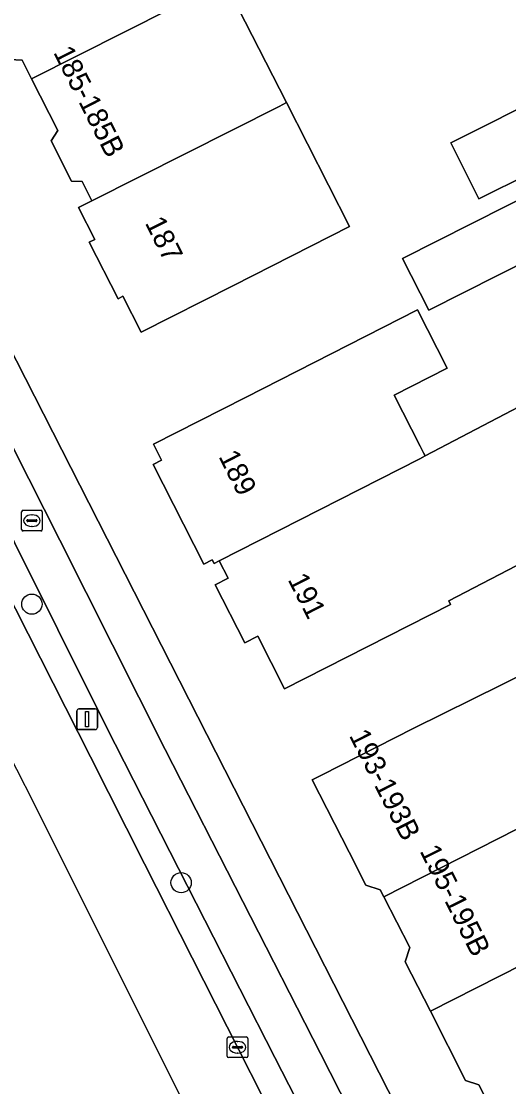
# Model space of a CAD drawing. Extents: x 162344 to 162869, y 381217 to 381818.
# Drawn here: x 162388.7 to 162412.2, y 381573.3 to 381624.8 of the extents above; entities that cross this region are included whole.
import ezdxf

# ---------------------------------------------------------------- set-up
doc = ezdxf.new("R2010")
doc.units = 0
for name, color, linetype in [('IMGEO_Berm_open', 7, 'Continuous'), ('IMGEO_Boom', 7, 'Continuous'), ('IMGEO_Brandkraan', 7, 'Continuous'), ('IMGEO_Erf', 7, 'Continuous'), ('IMGEO_Fietspad_open', 7, 'Continuous'), ('IMGEO_Kolk', 7, 'Continuous'), ('IMGEO_Lichtmast', 7, 'Continuous'), ('IMGEO_Pand', 7, 'Continuous'), ('IMGEO_Pand_nummerreeks', 7, 'Continuous'), ('IMGEO_Rijbaan_regionaal_gesloten', 7, 'Continuous'), ('IMGEO_Voetpad_open', 7, 'Continuous')]:
    doc.layers.add(name, color=color, linetype=linetype)

msp = doc.modelspace()

# ---------------------------------------------------------------- linework, layer by layer
at = {"layer": 'IMGEO_Berm_open'}
for points in [[(162358.654, 381655.431), (162360.733, 381651.139), (162362.48, 381647.434), (162367.291, 381637.935), (162369.471, 381633.629), (162370.915, 381630.775), (162376.144, 381620.551), (162378.309, 381616.304), (162381.2, 381610.636), (162383.842, 381605.454), (162387.066, 381599.034), (162387.783, 381597.606), (162391.996, 381589.28), (162394.619, 381584.098), (162396.915, 381579.56), (162402.557, 381568.4), (162406.049, 381561.587), (162408.71, 381556.396), (162409.049, 381555.709), (162410.306, 381556.355), (162407.33, 381562.188), (162400.899, 381574.731)], [(162400.899, 381574.731), (162395.837, 381584.693), (162393.201, 381589.881), (162392.517, 381591.227), (162388.339, 381599.637), (162387.808, 381600.705), (162382.464, 381611.316), (162380.864, 381614.494), (162379.579, 381616.989), (162374.942, 381625.996), (162370.754, 381634.243), (162367.724, 381640.204), (162364.002, 381647.524), (162361.111, 381653.216)]]:
    msp.add_lwpolyline(points, dxfattribs=at)
at = {"layer": 'IMGEO_Boom'}
for centre in [(162389.173, 381596.654), (162396.379, 381583.19)]:
    msp.add_circle(centre, 0.489, dxfattribs=at)
at = {"layer": 'IMGEO_Brandkraan'}
for p, q in [((162388.675, 381600.263), (162388.675, 381601.115)), ((162388.75, 381601.189), (162389.602, 381601.189)), ((162389.676, 381601.115), (162389.676, 381600.263)), ((162388.934, 381600.683), (162388.934, 381600.695)), ((162389.372, 381600.646), (162388.974, 381600.646)), ((162388.977, 381600.732), (162389.375, 381600.732)), ((162389.163, 381600.969), (162389.188, 381600.969)), ((162389.418, 381600.695), (162389.418, 381600.683)), ((162389.602, 381600.189), (162388.75, 381600.189)), ((162389.186, 381600.409), (162389.161, 381600.409))]:
    msp.add_line(p, q, dxfattribs=at)
for points in [[(162388.675, 381600.263), (162388.675, 381601.115)], [(162388.75, 381601.189), (162389.602, 381601.189)], [(162389.676, 381601.115), (162389.676, 381600.263)], [(162389.602, 381600.189), (162388.75, 381600.189)]]:
    msp.add_lwpolyline(points, dxfattribs=at)
for centre, radius, start, end in [((162388.752, 381601.113), 0.0765, 91.552, 178.448), ((162388.752, 381601.113), 0.0765, 91.552, 178.448), ((162389.6, 381601.113), 0.0765, 1.552, 88.448), ((162389.6, 381601.113), 0.0765, 1.552, 88.448), ((162388.974, 381600.692), 0.0403, 85.8775, 175.7526), ((162388.971, 381600.682), 0.0366, 178.938, 274.7102), ((162389.375, 381600.689), 0.043, 264.8664, 352.4533), ((162389.379, 381600.694), 0.0386, 1.7309, 96.639), ((162388.752, 381600.265), 0.0765, 181.552, 268.448), ((162388.752, 381600.265), 0.0765, 181.552, 268.448), ((162389.6, 381600.265), 0.0765, 271.552, 358.448), ((162389.6, 381600.265), 0.0765, 271.552, 358.448)]:
    msp.add_arc(centre, radius, start, end, dxfattribs=at)
for centre, major_axis, ratio, start_param, end_param in [((162389.162, 381600.689), (-0.387, 0.002), 0.722429, 4.712389, 7.853982), ((162389.187, 381600.689), (-0.39, 0.002), 0.717154, 1.570796, 4.712389)]:
    msp.add_ellipse(centre, major_axis=major_axis, ratio=ratio, start_param=start_param, end_param=end_param, dxfattribs=at)
at = {"layer": 'IMGEO_Erf'}
for points in [[(162364.764, 381654.894), (162443.597, 381500)], [(162383.789, 381641.951), (162389.324, 381644.767), (162392.382, 381638.757), (162395.465, 381632.697), (162398.481, 381626.77), (162401.468, 381620.899), (162404.512, 381614.916), (162398.902, 381612.062), (162394.445, 381609.794), (162393.56, 381611.534), (162393.333, 381611.419), (162391.947, 381614.144), (162392.214, 381614.28), (162391.431, 381615.821), (162392.072, 381616.147), (162391.598, 381617.079), (162391.087, 381617.106), (162390.098, 381619.05), (162390.426, 381619.555), (162389.157, 381622.048), (162388.7, 381622.947), (162388.095, 381622.98)], [(162418.383, 381615.941), (162408.339, 381610.859), (162407.074, 381613.357), (162417.121, 381618.435)], [(162413.361, 381598.924), (162409.305, 381596.816), (162409.395, 381596.64), (162401.374, 381592.559), (162400.082, 381595.1), (162399.459, 381594.783), (162398.031, 381597.59), (162398.654, 381597.907), (162398.225, 381598.75), (162397.971, 381598.622), (162397.885, 381598.792), (162397.484, 381598.588), (162395.031, 381603.409), (162395.432, 381603.613), (162395.04, 381604.382), (162399.497, 381606.65), (162407.798, 381610.873), (162409.231, 381608.056), (162406.673, 381606.755), (162407.93, 381604.285), (162408.091, 381603.968), (162408.169, 381603.815), (162421.093, 381610.584)], [(162412, 381570.989), (162410.763, 381573.42), (162410.117, 381573.63), (162408.417, 381576.971), (162407.199, 381579.365), (162407.423, 381580.052), (162406.171, 381582.512), (162406, 381582.848), (162405.3, 381583.076), (162404.489, 381584.67), (162402.711, 381588.165), (162403.154, 381588.39), (162407.611, 381590.658), (162416.078, 381594.848)]]:
    msp.add_lwpolyline(points, dxfattribs=at)
msp.add_lwpolyline([(162414.319, 381621.414), (162415.676, 381618.696), (162410.76, 381616.241), (162409.403, 381618.959)], close=True, dxfattribs=at)
at = {"layer": 'IMGEO_Fietspad_open'}
for points in [[(162427.81, 381526.456), (162419.849, 381541.928), (162411.637, 381558.14), (162403.109, 381574.937), (162395.607, 381589.625), (162390.519, 381599.747), (162382.229, 381616.136), (162373.547, 381633.19), (162366.42, 381647.346), (162362.948, 381654.184)], [(162361.111, 381653.216), (162364.002, 381647.524), (162367.724, 381640.204), (162370.754, 381634.243), (162374.942, 381625.996), (162379.579, 381616.989), (162380.864, 381614.494), (162382.464, 381611.316), (162387.808, 381600.705), (162388.339, 381599.637), (162392.517, 381591.227), (162393.201, 381589.881), (162395.837, 381584.693), (162400.899, 381574.731), (162407.33, 381562.188)]]:
    msp.add_lwpolyline(points, dxfattribs=at)
at = {"layer": 'IMGEO_Kolk'}
for p, q in [((162398.602, 381574.808), (162398.602, 381575.66)), ((162398.677, 381575.734), (162399.529, 381575.734)), ((162399.09, 381575.514), (162399.115, 381575.514)), ((162399.603, 381575.66), (162399.603, 381574.808)), ((162398.861, 381575.228), (162398.861, 381575.24)), ((162399.299, 381575.191), (162398.901, 381575.191)), ((162398.904, 381575.277), (162399.302, 381575.277)), ((162399.113, 381574.954), (162399.088, 381574.954)), ((162399.345, 381575.24), (162399.345, 381575.228)), ((162399.529, 381574.734), (162398.677, 381574.734))]:
    msp.add_line(p, q, dxfattribs=at)
for points in [[(162398.602, 381574.808), (162398.602, 381575.66)], [(162398.677, 381575.734), (162399.529, 381575.734)], [(162399.603, 381575.66), (162399.603, 381574.808)], [(162399.529, 381574.734), (162398.677, 381574.734)]]:
    msp.add_lwpolyline(points, dxfattribs=at)
for centre, radius, start, end in [((162398.679, 381575.658), 0.0765, 91.552, 178.448), ((162398.679, 381575.658), 0.0765, 91.552, 178.448), ((162399.527, 381575.658), 0.0765, 1.552, 88.448), ((162399.527, 381575.658), 0.0765, 1.552, 88.448), ((162398.901, 381575.237), 0.0403, 85.8775, 175.7526), ((162398.898, 381575.227), 0.0366, 178.938, 274.7102), ((162399.302, 381575.234), 0.043, 264.8664, 352.4533), ((162399.306, 381575.239), 0.0386, 1.7309, 96.639), ((162398.679, 381574.81), 0.0765, 181.552, 268.448), ((162398.679, 381574.81), 0.0765, 181.552, 268.448), ((162399.527, 381574.81), 0.0765, 271.552, 358.448), ((162399.527, 381574.81), 0.0765, 271.552, 358.448)]:
    msp.add_arc(centre, radius, start, end, dxfattribs=at)
for centre, major_axis, ratio, start_param, end_param in [((162399.089, 381575.234), (-0.387, 0.002), 0.722429, 4.712389, 7.853982), ((162399.114, 381575.234), (-0.39, 0.002), 0.717154, 1.570796, 4.712389)]:
    msp.add_ellipse(centre, major_axis=major_axis, ratio=ratio, start_param=start_param, end_param=end_param, dxfattribs=at)
at = {"layer": 'IMGEO_Lichtmast'}
for p, q in [((162391.344, 381590.691), (162391.344, 381591.491)), ((162391.344, 381591.491), (162391.344, 381590.691)), ((162391.444, 381591.591), (162392.234, 381591.591)), ((162392.234, 381591.591), (162391.444, 381591.591)), ((162392.334, 381591.491), (162392.334, 381590.691)), ((162392.334, 381590.691), (162392.334, 381591.491)), ((162392.234, 381590.591), (162391.444, 381590.591)), ((162391.444, 381590.591), (162392.234, 381590.591))]:
    msp.add_line(p, q, dxfattribs=at)
msp.add_lwpolyline([(162391.764, 381591.466), (162391.914, 381591.466), (162391.914, 381590.716), (162391.764, 381590.716), (162391.764, 381591.466)], dxfattribs=at)
for centre, start, end in [((162391.444, 381591.491), 90, 180), ((162391.444, 381591.491), 90, 180), ((162392.234, 381591.491), 0, 90), ((162392.234, 381591.491), 360, 90), ((162391.444, 381590.691), 180, 270), ((162391.444, 381590.691), 180, 270), ((162392.234, 381590.691), 270, 0), ((162392.234, 381590.691), 270, 0)]:
    msp.add_arc(centre, 0.1, start, end, dxfattribs=at)
at = {"layer": 'IMGEO_Pand'}
for points in [[(162389.157, 381622.048), (162398.14, 381626.591), (162398.481, 381626.77), (162395.465, 381632.697), (162395.139, 381632.524), (162386.11, 381627.958), (162387.426, 381625.372), (162387.118, 381624.899), (162388.095, 381622.98), (162388.7, 381622.947)], [(162398.481, 381626.77), (162398.14, 381626.591), (162389.157, 381622.048), (162390.426, 381619.555), (162390.098, 381619.05), (162391.087, 381617.106), (162391.598, 381617.079), (162392.072, 381616.147), (162401.111, 381620.715), (162401.468, 381620.899)], [(162409.403, 381618.959), (162410.76, 381616.241), (162415.676, 381618.696), (162414.319, 381621.414)], [(162401.468, 381620.899), (162401.111, 381620.715), (162392.072, 381616.147), (162391.431, 381615.821), (162392.214, 381614.28), (162391.947, 381614.144), (162393.333, 381611.419), (162393.56, 381611.534), (162394.445, 381609.794), (162398.902, 381612.062), (162404.512, 381614.916)], [(162418.383, 381615.941), (162417.121, 381618.435), (162407.074, 381613.357), (162408.339, 381610.859)], [(162406.673, 381606.755), (162409.231, 381608.056), (162407.798, 381610.873), (162399.497, 381606.65), (162395.04, 381604.382), (162395.432, 381603.613), (162395.031, 381603.409), (162397.484, 381598.588), (162397.885, 381598.792), (162397.971, 381598.622), (162398.225, 381598.75), (162407.903, 381603.676), (162408.169, 381603.815), (162408.091, 381603.968), (162407.93, 381604.285)], [(162421.123, 381600.023), (162423.591, 381601.277), (162425.348, 381602.17), (162421.093, 381610.584), (162408.169, 381603.815), (162407.903, 381603.676), (162398.225, 381598.75), (162398.654, 381597.907), (162398.031, 381597.59), (162399.459, 381594.783), (162400.082, 381595.1), (162401.374, 381592.559), (162409.395, 381596.64), (162409.305, 381596.816), (162413.361, 381598.924), (162414.513, 381596.661), (162418.97, 381598.929), (162420.127, 381599.517)], [(162406.171, 381582.512), (162419.052, 381589.067), (162418.929, 381589.309), (162417.498, 381592.056), (162416.078, 381594.848), (162407.611, 381590.658), (162403.154, 381588.39), (162402.711, 381588.165), (162404.489, 381584.67), (162405.3, 381583.076), (162406, 381582.848)], [(162408.417, 381576.971), (162412.859, 381579.232), (162413.312, 381578.341), (162417.289, 381580.365), (162415.516, 381583.85), (162420.434, 381586.352), (162419.052, 381589.067), (162406.171, 381582.512), (162407.423, 381580.052), (162407.199, 381579.365)], [(162408.417, 381576.971), (162410.117, 381573.63), (162410.763, 381573.42), (162412, 381570.989), (162424.894, 381577.551), (162423.437, 381580.415), (162418.533, 381577.92), (162417.289, 381580.365), (162413.312, 381578.341), (162412.859, 381579.232)]]:
    msp.add_lwpolyline(points, close=True, dxfattribs=at)
at = {"layer": 'IMGEO_Rijbaan_regionaal_gesloten'}
for points in [[(162353.085, 381658.958), (162357.948, 381648.399), (162379.464, 381606.233), (162388.83, 381587.88), (162458.544, 381448.405), (162487.336, 381390.854)], [(162402.557, 381568.4), (162396.915, 381579.56), (162394.619, 381584.098), (162391.996, 381589.28), (162387.783, 381597.606), (162387.066, 381599.034), (162383.842, 381605.454), (162381.2, 381610.636), (162378.309, 381616.304), (162376.144, 381620.551), (162370.915, 381630.775), (162369.471, 381633.629), (162367.291, 381637.935), (162362.48, 381647.434), (162360.733, 381651.139), (162358.654, 381655.431)]]:
    msp.add_lwpolyline(points, dxfattribs=at)
at = {"layer": 'IMGEO_Voetpad_open'}
msp.add_lwpolyline([(162362.948, 381654.184), (162366.42, 381647.346), (162373.547, 381633.19), (162382.229, 381616.136), (162390.519, 381599.747), (162395.607, 381589.625), (162403.109, 381574.937), (162411.637, 381558.14), (162419.849, 381541.928), (162427.81, 381526.456), (162437.491, 381507.399), (162441.265, 381500), (162456.812, 381469.521), (162464.953, 381453.521), (162466.79, 381454.429), (162443.597, 381500), (162364.764, 381654.894)], dxfattribs=at)

# ---------------------------------------------------------------- texts
at = {"layer": 'IMGEO_Pand_nummerreeks'}
for s, rotation, p in [('185-185B', 296.9746, (162390.189, 381623.328)), ('187', 296.5688, (162394.616, 381615.087)), ('189', 296.9689, (162398.168, 381603.793)), ('191', 296.9632, (162401.513, 381597.844)), ('193-193B', 296.8977, (162404.473, 381590.302)), ('195-195B', 296.4192, (162407.887, 381584.723))]:
    msp.add_text(s, height=1, rotation=rotation, dxfattribs=at).set_placement(p)

doc.saveas('drawing.dxf')
